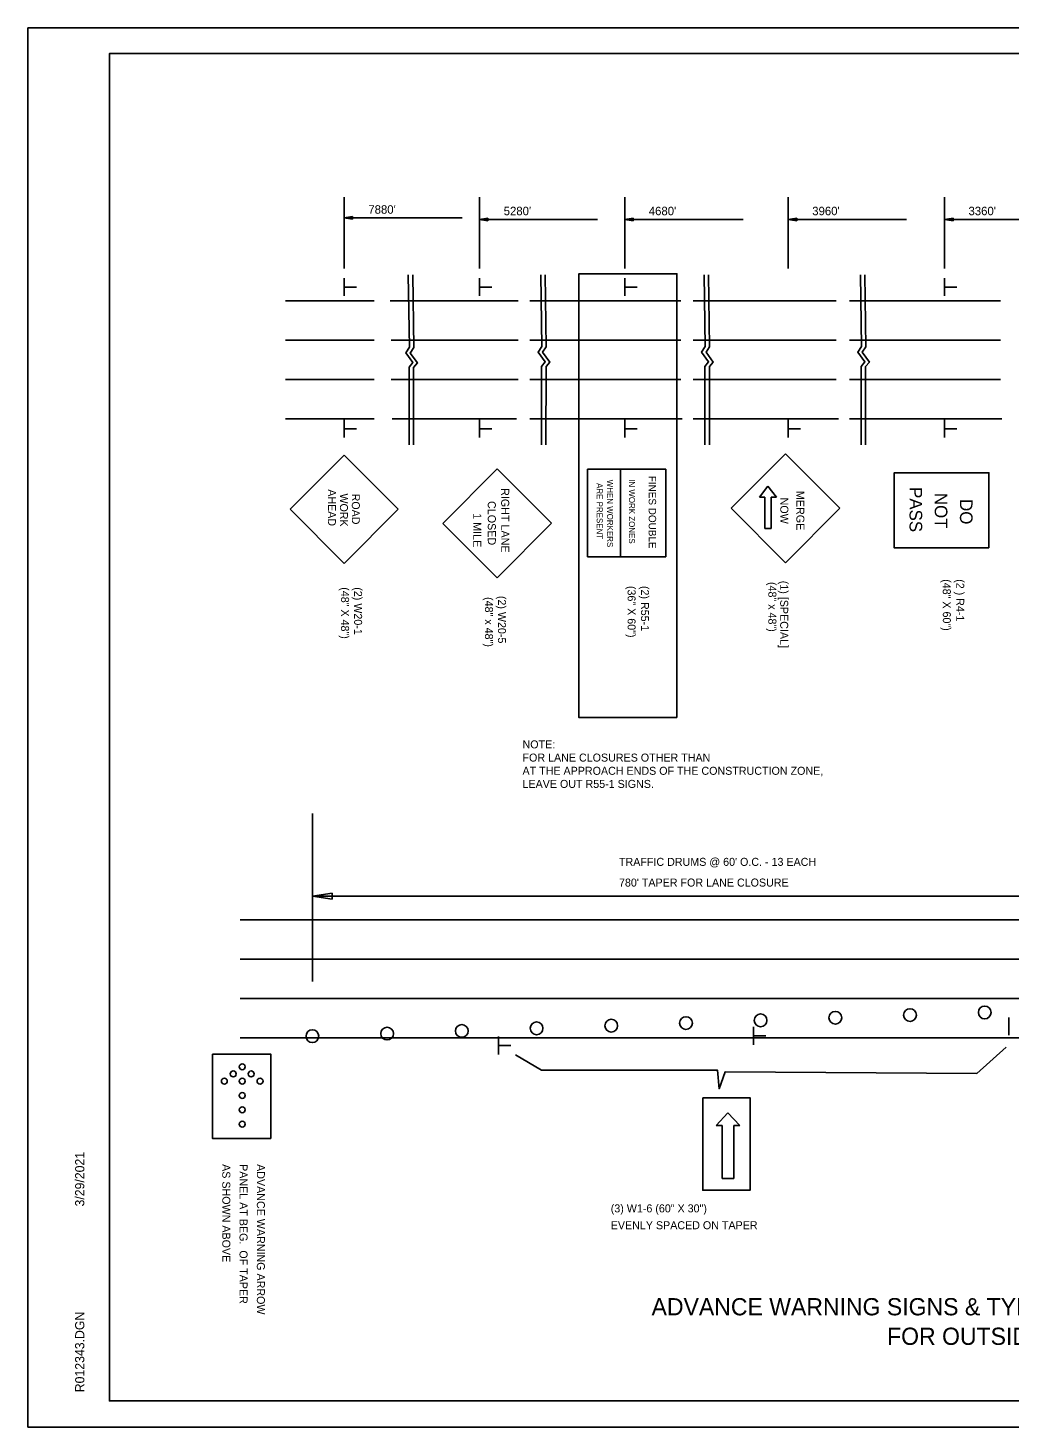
# Model space of a CAD drawing. Extents: x 1397271 to 1411271, y 376395 to 377888.
# Drawn here: x 1401938 to 1402985, y 376395 to 377888 of the extents above; entities that cross this region are included whole.
import ezdxf

# ---------------------------------------------------------------- set-up
doc = ezdxf.new("R2010")
doc.units = 0
for name, color, linetype in [('Default', 7, 'Continuous'), ('R_Border', 7, 'Continuous'), ('R_MOT', 7, 'Continuous'), ('R_No Plot', 7, 'Continuous')]:
    doc.layers.add(name, color=color, linetype=linetype)

msp = doc.modelspace()

# ---------------------------------------------------------------- linework, layer by layer
at = {"layer": 'Default'}
for p, q in [((1402275.2, 377707.3), (1402275.2, 377631.1)), ((1402419.8, 377707.3), (1402419.8, 377631.1)), ((1402574.9, 377707.3), (1402574.9, 377631.1)), ((1402749.3, 377707.3), (1402749.3, 377631.1)), ((1402916.2, 377707.3), (1402916.2, 377631.1)), ((1402284.3, 377686.6), (1402275.2, 377685.3)), ((1402275.2, 377685.3), (1402401.4, 377685.3)), ((1402284.3, 377683.9), (1402275.2, 377685.3)), ((1402284.3, 377686.4), (1402276.8, 377685.3)), ((1402284.3, 377684.1), (1402276.8, 377685.3)), ((1402284.3, 377686.2), (1402278.3, 377685.3)), ((1402284.3, 377684.3), (1402278.3, 377685.3)), ((1402284.3, 377685.9), (1402279.8, 377685.3)), ((1402284.3, 377684.6), (1402279.8, 377685.3)), ((1402284.3, 377685.7), (1402281.4, 377685.3)), ((1402284.3, 377684.8), (1402281.4, 377685.3)), ((1402284.3, 377685.5), (1402282.9, 377685.3)), ((1402284.3, 377685), (1402282.9, 377685.3)), ((1402284.3, 377683.9), (1402284.3, 377686.6)), ((1402428.8, 377685), (1402419.8, 377683.6)), ((1402419.8, 377683.6), (1402545.9, 377683.6)), ((1402428.8, 377682.3), (1402419.8, 377683.6)), ((1402428.8, 377684.8), (1402421.3, 377683.6)), ((1402428.8, 377682.5), (1402421.3, 377683.6)), ((1402428.8, 377684.5), (1402422.8, 377683.6)), ((1402428.8, 377682.7), (1402422.8, 377683.6)), ((1402428.8, 377684.3), (1402424.3, 377683.6)), ((1402428.8, 377683), (1402424.3, 377683.6)), ((1402428.8, 377684.1), (1402425.9, 377683.6)), ((1402428.8, 377683.2), (1402425.9, 377683.6)), ((1402428.8, 377683.9), (1402427.4, 377683.6)), ((1402428.8, 377683.4), (1402427.4, 377683.6)), ((1402428.8, 377682.3), (1402428.8, 377685)), ((1402584, 377685), (1402574.9, 377683.6)), ((1402574.9, 377683.6), (1402701.1, 377683.6)), ((1402584, 377682.3), (1402574.9, 377683.6)), ((1402584, 377684.8), (1402576.4, 377683.6)), ((1402584, 377682.5), (1402576.4, 377683.6)), ((1402584, 377684.5), (1402578, 377683.6)), ((1402584, 377682.7), (1402578, 377683.6)), ((1402584, 377684.3), (1402579.5, 377683.6)), ((1402584, 377683), (1402579.5, 377683.6)), ((1402584, 377684.1), (1402581, 377683.6)), ((1402584, 377683.2), (1402581, 377683.6)), ((1402584, 377683.9), (1402582.5, 377683.6)), ((1402584, 377683.4), (1402582.5, 377683.6)), ((1402584, 377682.3), (1402584, 377685)), ((1402758.4, 377685), (1402749.3, 377683.6)), ((1402749.3, 377683.6), (1402875.5, 377683.6)), ((1402758.4, 377682.3), (1402749.3, 377683.6)), ((1402758.4, 377684.8), (1402750.9, 377683.6)), ((1402758.4, 377682.5), (1402750.9, 377683.6)), ((1402758.4, 377684.5), (1402752.4, 377683.6)), ((1402758.4, 377682.7), (1402752.4, 377683.6)), ((1402758.4, 377684.3), (1402753.9, 377683.6)), ((1402758.4, 377683), (1402753.9, 377683.6)), ((1402758.4, 377684.1), (1402755.5, 377683.6)), ((1402758.4, 377683.2), (1402755.5, 377683.6)), ((1402758.4, 377683.9), (1402757, 377683.6)), ((1402758.4, 377683.4), (1402757, 377683.6)), ((1402758.4, 377682.3), (1402758.4, 377685)), ((1402925.3, 377685), (1402916.2, 377683.6)), ((1402916.2, 377683.6), (1403042.4, 377683.6)), ((1402925.3, 377682.3), (1402916.2, 377683.6)), ((1402925.3, 377684.8), (1402917.7, 377683.6)), ((1402925.3, 377682.5), (1402917.7, 377683.6)), ((1402925.3, 377684.5), (1402919.3, 377683.6)), ((1402925.3, 377682.7), (1402919.3, 377683.6)), ((1402925.3, 377684.3), (1402920.8, 377683.6)), ((1402925.3, 377683), (1402920.8, 377683.6)), ((1402925.3, 377684.1), (1402922.3, 377683.6)), ((1402925.3, 377683.2), (1402922.3, 377683.6)), ((1402925.3, 377683.9), (1402923.8, 377683.6)), ((1402925.3, 377683.4), (1402923.8, 377683.6)), ((1402925.3, 377682.3), (1402925.3, 377685)), ((1402212.7, 377596.8), (1402307.5, 377596.8)), ((1402324.4, 377596.8), (1402461, 377596.8)), ((1402473.5, 377596.8), (1402634.6, 377596.8)), ((1402647.9, 377596.8), (1402800.7, 377596.8)), ((1402814.7, 377596.8), (1402975.9, 377596.8)), ((1402212.7, 377554.8), (1402307.5, 377554.8)), ((1402325.5, 377554.8), (1402461, 377554.8)), ((1402473.5, 377554.8), (1402634.6, 377554.8)), ((1402647.9, 377554.8), (1402800.7, 377554.8)), ((1402814.7, 377554.8), (1402975.9, 377554.8)), ((1402212.7, 377512.7), (1402307.5, 377512.7)), ((1402325.5, 377512.7), (1402461, 377512.7)), ((1402473.5, 377512.7), (1402634.6, 377512.7)), ((1402647.9, 377512.7), (1402800.7, 377512.7)), ((1402814.7, 377512.7), (1402975.9, 377512.7)), ((1402212.7, 377470.7), (1402307.5, 377470.7)), ((1402326.6, 377470.7), (1402459.3, 377470.7)), ((1402473.5, 377470.7), (1402636, 377470.7)), ((1402647.9, 377470.7), (1402802.9, 377470.7)), ((1402814.7, 377470.7), (1402977.3, 377470.7)), ((1402241.4, 377049.4), (1402241.4, 376870.1)), ((1402241.4, 376961.1), (1402262.4, 376964.3)), ((1402262.4, 376964.3), (1402262.4, 376958)), ((1403257.1, 376961.1), (1402241.4, 376961.1)), ((1402262.4, 376958), (1402241.4, 376961.1)), ((1402164.2, 376936), (1402218.9, 376936)), ((1402218.9, 376936), (1403856.5, 376936)), ((1402164.2, 376893.9), (1402218.9, 376893.9)), ((1402218.9, 376893.9), (1403856.5, 376893.9)), ((1402164.2, 376851.9), (1402218.9, 376851.9)), ((1402218.9, 376851.9), (1403856.5, 376851.9)), ((1402164.2, 376809.9), (1402218.9, 376809.9)), ((1402218.9, 376809.9), (1403856.5, 376809.9))]:
    msp.add_line(p, q, dxfattribs=at)
msp.add_lwpolyline([(1402458.1, 376791.9), (1402486.1, 376775.4), (1402673.9, 376775.4), (1402675.5, 376755.6), (1402682.1, 376773.8), (1402950.6, 376772.1), (1402981.9, 376800.1)], dxfattribs=at)
at = {"layer": 'R_Border'}
for p, q in [((1402024.6, 377860.7), (1404237.9, 377860.7)), ((1402024.6, 376422.5), (1402024.6, 377860.7)), ((1402024.6, 376422.5), (1402024.6, 376422.5)), ((1404237.9, 376422.5), (1402024.6, 376422.5))]:
    msp.add_line(p, q, dxfattribs=at)
at = {"layer": 'R_MOT'}
for p, q in [((1402275.2, 377602), (1402275.2, 377620.9)), ((1402419.8, 377602), (1402419.8, 377620.9)), ((1402574.9, 377602), (1402574.9, 377620.9)), ((1402916.2, 377602), (1402916.2, 377620.9)), ((1402275.5, 377611.4), (1402288.4, 377611.4)), ((1402420, 377611.4), (1402432.9, 377611.4)), ((1402575.2, 377611.4), (1402588.1, 377611.4)), ((1402916.5, 377611.4), (1402929.4, 377611.4)), ((1402275.2, 377450.7), (1402275.2, 377469.6)), ((1402419.8, 377450.7), (1402419.8, 377469.6)), ((1402574.9, 377450.7), (1402574.9, 377469.6)), ((1402749.3, 377450.7), (1402749.3, 377469.6)), ((1402916.2, 377450.7), (1402916.2, 377469.6)), ((1402275.5, 377460.1), (1402288.4, 377460.1)), ((1402420, 377460.1), (1402432.9, 377460.1)), ((1402575.2, 377460.1), (1402588.1, 377460.1)), ((1402749.6, 377460.1), (1402762.5, 377460.1)), ((1402916.5, 377460.1), (1402929.4, 377460.1)), ((1402217.6, 377374.2), (1402275.3, 377432)), ((1402275.3, 377432), (1402333.1, 377374.2)), ((1402688.4, 377375.3), (1402746.4, 377433.5)), ((1402746.4, 377433.5), (1402804.6, 377375.5)), ((1402380.5, 377359.2), (1402438.6, 377417.5)), ((1402438.6, 377417.5), (1402496.8, 377359.4)), ((1402570.2, 377323.6), (1402570.2, 377417)), ((1402718.6, 377387), (1402727.7, 377398.8)), ((1402727.7, 377398.8), (1402736.7, 377387)), ((1402724.3, 377387), (1402718.6, 377387)), ((1402724.3, 377353.6), (1402724.3, 377387)), ((1402731.1, 377387), (1402731.1, 377353.6)), ((1402736.7, 377387), (1402731.1, 377387)), ((1402275.3, 377316.4), (1402217.6, 377374.2)), ((1402333.1, 377374.2), (1402275.3, 377316.4)), ((1402746.6, 377317.2), (1402688.4, 377375.3)), ((1402804.6, 377375.5), (1402746.6, 377317.2)), ((1402438.8, 377301.2), (1402380.5, 377359.2)), ((1402496.8, 377359.4), (1402438.8, 377301.2)), ((1402731.1, 377353.6), (1402724.3, 377353.6)), ((1402985, 376813), (1402985, 376831.9)), ((1402712.4, 376802.7), (1402712.4, 376821.6)), ((1402439.9, 376792.4), (1402439.9, 376811.3)), ((1402440.2, 376801.8), (1402453.1, 376801.8)), ((1402712.7, 376812.1), (1402725.6, 376812.1)), ((1402672.5, 376716.3), (1402685, 376730.1)), ((1402685, 376730.1), (1402697.6, 376716.3)), ((1402678.7, 376716.3), (1402672.5, 376716.3)), ((1402678.7, 376659.9), (1402678.7, 376716.3)), ((1402691.3, 376659.9), (1402691.3, 376716.3)), ((1402691.3, 376716.3), (1402697.6, 376716.3)), ((1402678.7, 376659.9), (1402691.3, 376659.9))]:
    msp.add_line(p, q, dxfattribs=at)
for points in [[(1402343.7, 377624.6), (1402344.9, 377547.1), (1402341, 377541.2), (1402348.6, 377530.8), (1402344.6, 377525.9), (1402344.6, 377442.9)], [(1402348.6, 377624.6), (1402349.7, 377546.9), (1402345.8, 377541), (1402353.5, 377530.6), (1402349.4, 377525.7), (1402349.4, 377442.9)], [(1402485.1, 377624.6), (1402486.2, 377547.9), (1402482.3, 377542), (1402489.9, 377531.6), (1402485.9, 377526.7), (1402485.9, 377442.9)], [(1402489.9, 377624.6), (1402491.1, 377547.7), (1402487.1, 377541.8), (1402494.8, 377531.4), (1402490.8, 377526.5), (1402490.7, 377442.9)], [(1402659.5, 377624.6), (1402660.7, 377547.9), (1402656.8, 377542), (1402664.4, 377531.6), (1402660.4, 377526.7), (1402660.4, 377442.9)], [(1402664.3, 377624.6), (1402665.5, 377547.7), (1402661.6, 377541.8), (1402669.2, 377531.4), (1402665.2, 377526.5), (1402665.2, 377442.9)], [(1402826.4, 377624.6), (1402827.5, 377547.9), (1402823.6, 377542), (1402831.2, 377531.6), (1402827.2, 377526.7), (1402827.2, 377442.9)], [(1402831.2, 377624.6), (1402832.4, 377547.7), (1402828.4, 377541.8), (1402836.1, 377531.4), (1402832, 377526.5), (1402832, 377442.9)]]:
    msp.add_lwpolyline(points, dxfattribs=at)
for points in [[(1402630.6, 377151.8), (1402526, 377151.8), (1402526, 377625.6), (1402630.6, 377625.6)], [(1402618.6, 377417), (1402535.2, 377417), (1402535.2, 377323.6), (1402618.6, 377323.6)], [(1402963.7, 377333), (1402862.6, 377333), (1402862.6, 377413.2), (1402963.7, 377413.2)], [(1402134.6, 376792.6), (1402134.6, 376702.6), (1402196.9, 376702.6), (1402196.9, 376792.6)], [(1402658.1, 376746.1), (1402658.1, 376647.3), (1402708.6, 376647.3), (1402708.6, 376746.1)]]:
    msp.add_lwpolyline(points, close=True, dxfattribs=at)
for centre, radius in [((1402959.2, 376837.1), 6.8), ((1402560.4, 376823), 6.8), ((1402640.2, 376825.8), 6.8), ((1402719.9, 376828.7), 6.8), ((1402799.7, 376831.5), 6.8), ((1402879.4, 376834.3), 6.8), ((1402241.4, 376811.8), 6.8), ((1402321.2, 376814.6), 6.8), ((1402400.9, 376817.4), 6.8), ((1402480.7, 376820.2), 6.8), ((1402156.9, 376771.5), 3.17), ((1402166.5, 376779.1), 3.17), ((1402176, 376771.5), 3.17), ((1402147.4, 376763.8), 3.17), ((1402166.5, 376763.8), 3.17), ((1402185.5, 376763.8), 3.17), ((1402166.5, 376748.5), 3.17), ((1402166.5, 376733.2), 3.17), ((1402166.5, 376717.9), 3.17)]:
    msp.add_circle(centre, radius, dxfattribs=at)
at = {"layer": 'R_No Plot'}
for p, q in [((1401937.8, 377888), (1404271.1, 377888)), ((1401937.8, 376394.6), (1404271.1, 376394.6))]:
    msp.add_line(p, q, dxfattribs=at)
for points in [[(1401937.7, 377888), (1404271.1, 377888), (1404271.1, 376394.6), (1401937.7, 376394.6)], [(1403662, 377860.7), (1403662, 377791.6), (1403912.2, 377791.6), (1403912.2, 377771.1), (1404074.6, 377771.1), (1404074.6, 377600.8), (1404237.9, 377600.8), (1404237.9, 376422.5), (1402024.6, 376422.5), (1402024.6, 377860.7)]]:
    msp.add_lwpolyline(points, close=True, dxfattribs=at)

# ---------------------------------------------------------------- texts
at = {"layer": 'Default'}
for s, height, p in [("7880'", 9.07, (1402301.1, 377689.7)), ("5280'", 9.07, (1402445.6, 377688.1)), ("4680'", 9.07, (1402600.5, 377688.1)), ("3960'", 9.07, (1402775, 377688.1)), ("3360'", 9.07, (1402941.8, 377688.1)), ('NOTE:', 8.54, (1402465.7, 377119)), ('FOR LANE CLOSURES OTHER THAN ', 8.54, (1402465.7, 377104.9)), ('AT THE APPROACH ENDS OF THE CONSTRUCTION ZONE,', 8.54, (1402465.7, 377090.8)), ('LEAVE OUT R55-1 SIGNS.', 8.54, (1402465.7, 377076.8)), ("TRAFFIC DRUMS @ 60' O.C. - 13 EACH", 8.54, (1402568.7, 376993.6)), ("780' TAPER FOR LANE CLOSURE", 8.54, (1402568.7, 376971.5)), ('ADVANCE WARNING SIGNS & TYPICAL TRAFFIC DRUM PLACEMENT', 18.375, (1402603.5, 376513.8)), ('FOR OUTSIDE LANE CLOSURE', 18.375, (1402854.9, 376482.3))]:
    msp.add_text(s, height=height, dxfattribs=at).set_placement(p)
at = {"layer": 'R_Border'}
for s, p in [('3/29/2021', (1401997.9, 376630)), ('R012343.DGN', (1401997.9, 376431.7))]:
    msp.add_text(s, height=9.8, rotation=90, dxfattribs=at).set_placement(p)
at = {"layer": 'R_MOT'}
for s, height, rotation, p in [(' AHEAD', 8.51, 270.0006, (1402258, 377398.7)), ('RIGHT LANE', 8.57, 270.1004, (1402442.9, 377396.8)), ('ARE PRESENT', 6.34, 270, (1402544.9, 377402.2)), ('WHEN WORKERS', 6.34, 270, (1402556, 377405.8)), ('IN WORK ZONES', 6.339, 270, (1402579.3, 377406.3)), ('FINES DOUBLE', 7.925, 270, (1402600.4, 377410)), ('PASS', 13.46, 270, (1402878.9, 377397.9)), ('WORK', 8.51, 270, (1402270.8, 377391.1)), ('ROAD', 8.51, 270.0004, (1402283.5, 377390.9)), ('CLOSED', 8.57, 270.1003, (1402428.6, 377383)), ('NOW', 8.57, 270.1003, (1402740.9, 377386.7)), ('MERGE', 8.57, 270.1004, (1402758, 377393.8)), ('NOT', 13.46, 270, (1402905.8, 377391.7)), ('DO', 13.46, 270, (1402932.7, 377385.1)), ('1 MILE', 8.62, 270.0006, (1402413.1, 377370.1)), ('(36" X 60")', 8.54, 270, (1402577.9, 377292.4)), ('(2) R55-1', 8.54, 270, (1402592.2, 377292.4)), ('(48" x 48")', 8.54, 270, (1402728.2, 377296.6)), ('(1) [SPECIAL]', 8.54, 270, (1402740.8, 377297.9)), ('(48" X 60")', 8.54, 270, (1402914.4, 377299.6)), ('(2 ) R4-1', 8.54, 270, (1402928.7, 377299.6)), ('(48" X 48")', 8.54, 270, (1402272, 377291)), ('(2) W20-1', 8.54, 270, (1402285.9, 377291)), ('(48" x 48")', 8.54, 270, (1402425.6, 377280.5)), ('(2) W20-5', 8.54, 270, (1402439.5, 377281.8)), ('AS SHOWN ABOVE', 8.54, 270, (1402145.2, 376675.2)), ('PANEL AT BEG.  OF TAPER', 8.54, 270, (1402163.6, 376675.2)), ('ADVANCE WARNING ARROW', 8.54, 270, (1402182.1, 376675.2)), ('(3) W1-6 (60" X 30")', 8.54, 0.0075, (1402559.9, 376623.7)), ('EVENLY SPACED ON TAPER', 8.54, 0.0075, (1402559.9, 376605.7))]:
    msp.add_text(s, height=height, rotation=rotation, dxfattribs=at).set_placement(p)

doc.saveas('drawing.dxf')
